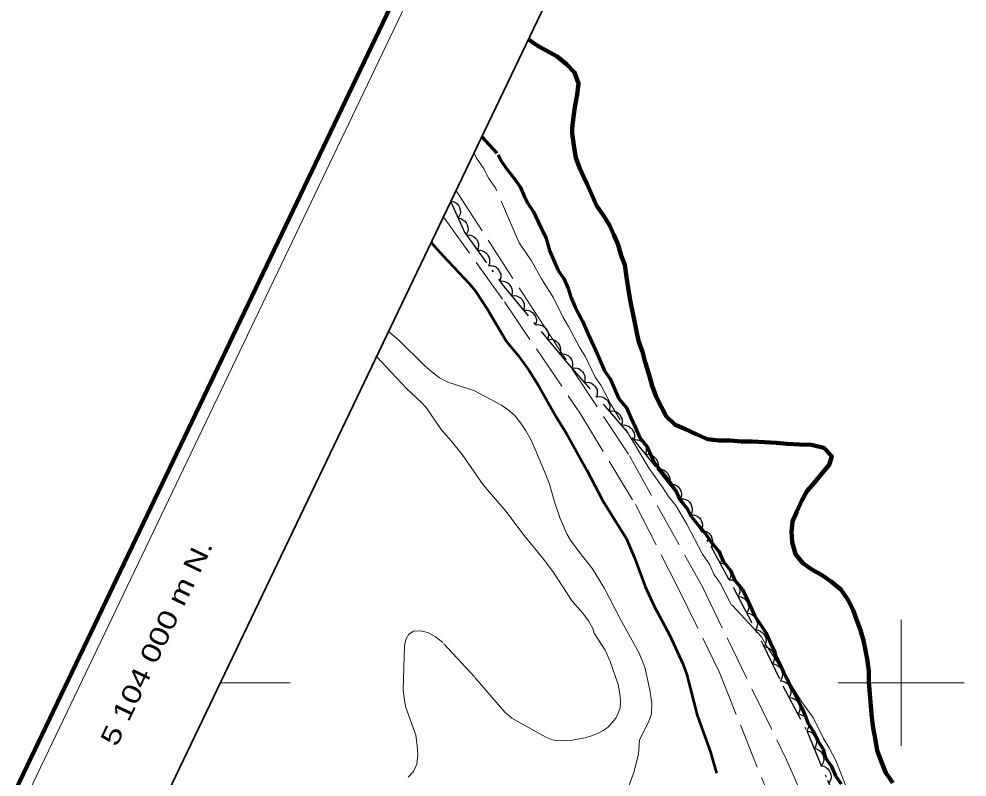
# Model space of a CAD drawing. Extents: x 356765 to 358572, y 5103174 to 5104650.
# Drawn here: x 356830 to 356905.2, y 5103992.5 to 5104052.7 of the extents above; entities that cross this region are included whole.
import ezdxf
from ezdxf.enums import TextEntityAlignment as Align

# ---------------------------------------------------------------- set-up
doc = ezdxf.new("R2010")
doc.units = 0
doc.header["$LTSCALE"] = 0.6
for name, pattern in [('DOT_DASHED', [7.7, 5, -1.2, 0.3, -1.2]), ('LONG_DASHED', [7.5, 6, -1.5]), ('MEDIUM_DASHED', [4.5, 3, -1.5])]:
    doc.linetypes.add(name, pattern=pattern)
for name, color, linetype, lineweight in [('1', 7, 'Continuous', 53), ('2', 7, 'Continuous', 13), ('4', 7, 'Continuous', 90), ('44', 7, 'Continuous', 25), ('60', 7, 'Continuous', 13), ('61', 7, 'Continuous', 13), ('7', 7, 'MEDIUM_DASHED', 70)]:
    doc.layers.add(name, color=color, linetype=linetype, lineweight=lineweight)

msp = doc.modelspace()

# ---------------------------------------------------------------- linework, layer by layer
at = {"layer": '1', "linetype": 'LONG_DASHED'}
msp.add_lwpolyline([(356862.66, 5104035.01), (356863.6, 5104033.95), (356865.74, 5104031.69), (356866.24, 5104031.07), (356867.12, 5104029.7), (356868.66, 5104027.12), (356869.59, 5104026), (356870.45, 5104024.82), (356871.21, 5104023.61), (356872.62, 5104021.13), (356873.44, 5104019.8), (356875.05, 5104016.88), (356876.32, 5104014.45), (356878.16, 5104011.5), (356878.8, 5104010), (356879.69, 5104007.65), (356880.4, 5104006.09), (356881.6, 5104003.8), (356882.71, 5104001.44), (356882.98, 5104000.63), (356883.81, 5103997.43), (356884.86, 5103994.49), (356885.34, 5103992.82)], dxfattribs=at)
at = {"layer": '2', "linetype": 'LONG_DASHED'}
for points in [[(356886.62, 5104006.13), (356886.54, 5104006.17), (356885.68, 5104007.83), (356885.14, 5104008.63), (356884.79, 5104009.42), (356884.24, 5104010.22), (356882.99, 5104012.6), (356882.12, 5104014.07), (356881.53, 5104014.79), (356881.06, 5104015.55), (356880, 5104017.03), (356876.97, 5104022.08), (356876.15, 5104023.63), (356875.71, 5104024.27), (356874.93, 5104025.89), (356874.46, 5104026.65), (356873.6, 5104028.31), (356873.13, 5104029.07), (356872.39, 5104030.57), (356871.44, 5104032.08), (356870.66, 5104033.51), (356869.67, 5104034.95), (356867.81, 5104039.25), (356867.26, 5104040.05), (356866.83, 5104040.88), (356866.29, 5104041.68), (356866.08, 5104042.13)], [(356864.64, 5104039.12), (356864.78, 5104038.93), (356871.41, 5104028.67), (356878.44, 5104018.03), (356884.22, 5104007.61), (356890.91, 5103993.87), (356897.31, 5103979.51), (356902.18, 5103967.99), (356905.03, 5103961.08), (356905.73, 5103956.92), (356906.05, 5103951.45), (356907.04, 5103946.26), (356907.65, 5103944.38), (356908.61, 5103941.88), (356909.24, 5103940.54), (356910.06, 5103938.2), (356910.5, 5103936.09)], [(356863.64, 5104037.05), (356868.51, 5104030.25), (356874.49, 5104021.45), (356878.9, 5104014.17), (356882.28, 5104007.58), (356885.58, 5104000.83), (356889.17, 5103991.84), (356894.82, 5103979.94)], [(356859.27, 5104027.93), (356860.09, 5104027.25), (356862.18, 5104025.17), (356862.75, 5104024.69), (356863.36, 5104024.22), (356864.02, 5104023.88), (356866.07, 5104023.22), (356868.28, 5104022.05), (356868.8, 5104021.68), (356869.32, 5104021.23), (356869.79, 5104020.66), (356870.2, 5104020.01), (356870.59, 5104019.33), (356870.92, 5104018.62), (356871.83, 5104016.47), (356872.08, 5104015.78), (356872.47, 5104014.38), (356872.93, 5104013.05), (356873.45, 5104011.84), (356873.75, 5104011.33), (356874.4, 5104010.42), (356875.5, 5104009.04), (356876.46, 5104007.5), (356877.67, 5104005.13), (356879.2, 5104002.34), (356879.64, 5104001.24), (356880.06, 5103999.45), (356880.21, 5103998.38), (356880.19, 5103997.54), (356879.94, 5103996.88), (356879.22, 5103995.47), (356879.15, 5103994.34), (356878.77, 5103992.88), (356878.31, 5103991.58)], [(356858.32, 5104025.96), (356858.35, 5104025.93), (356860.72, 5104023.38), (356861.95, 5104022.24), (356862.28, 5104021.88), (356863.49, 5104020.13), (356864.28, 5104019.22), (356865.14, 5104018.13), (356866.81, 5104015.72), (356868.61, 5104013.63), (356870.08, 5104011.71), (356871.64, 5104009.78), (356872.39, 5104008.75), (356873.88, 5104006.49), (356874.73, 5104005.53), (356875.18, 5104004.91), (356875.52, 5104004.3), (356875.63, 5104003.94), (356876.5, 5104002.59), (356876.91, 5104001.7), (356877.54, 5103999.86), (356877.7, 5103998.95), (356877.73, 5103998.47), (356877.69, 5103998.01), (356877.54, 5103997.59), (356877.34, 5103997.2), (356876.75, 5103996.48), (356876.35, 5103996.2), (356875.89, 5103995.98), (356875.43, 5103995.78), (356874.92, 5103995.63), (356873.89, 5103995.45), (356872.83, 5103995.38), (356872.32, 5103995.46), (356871.79, 5103995.68), (356869.08, 5103997.19), (356868.53, 5103997.66), (356866.14, 5104000.45), (356863.61, 5104003.19), (356863.04, 5104003.65), (356862.41, 5104004), (356861.8, 5104004.13), (356861.28, 5104004.09), (356860.92, 5104003.86), (356860.68, 5104003.45), (356860.57, 5104002.93), (356860.46, 5103999.44), (356860.53, 5103998.76), (356860.68, 5103998.05), (356861.47, 5103995.83), (356861.58, 5103995.01), (356861.63, 5103994.24), (356861.54, 5103993.53), (356861.29, 5103992.95), (356860.86, 5103992.49)]]:
    msp.add_lwpolyline(points, dxfattribs=at)
at = {"layer": '2'}
for points in [[(356894.83, 5103993.83), (356894.3, 5103994.82), (356893.83, 5103995.58), (356893.05, 5103997.2), (356892.1, 5103998.52), (356889.85, 5104002.15), (356889.31, 5104002.94), (356888.91, 5104003.66), (356886.62, 5104006.13)], [(356912.18, 5103936.61), (356911.1, 5103939.29), (356909.98, 5103942.98), (356909.67, 5103943.84), (356907.82, 5103951), (356907.01, 5103953.83), (356906.63, 5103955.62), (356905.82, 5103958.44), (356905.63, 5103959.34), (356905.33, 5103961.29), (356903.99, 5103965.99), (356903.84, 5103966.96), (356903.14, 5103969.63), (356903.03, 5103970.48), (356902.52, 5103972.25), (356902.14, 5103974.04), (356901.87, 5103974.98), (356900.35, 5103979.19), (356900.08, 5103980.13), (356899.69, 5103981.04), (356899.43, 5103981.98), (356898.56, 5103984.34), (356894.83, 5103993.83)]]:
    msp.add_lwpolyline(points, dxfattribs=at)
at = {"layer": '4'}
for points in [[(356870.39, 5104051.12), (356871.11, 5104050.63), (356871.87, 5104050.2), (356872.7, 5104049.74), (356873.45, 5104049.12), (356874.08, 5104048.48), (356874.39, 5104047.61), (356874.27, 5104046.69), (356874.12, 5104045.88), (356874, 5104044.96), (356873.88, 5104044.04), (356873.87, 5104043.65), (356874.02, 5104042.68), (356874.17, 5104041.7), (356874.48, 5104040.84), (356874.8, 5104040.16), (356875.08, 5104039.61), (356875.82, 5104037.91), (356876.37, 5104037.11), (356876.84, 5104036.36), (356877.19, 5104035.57), (356877.54, 5104034.78), (356877.78, 5104033.95), (356878.06, 5104033.2), (356878.21, 5104032.23), (356878.32, 5104031.37), (356878.48, 5104030.4), (356878.67, 5104029.5), (356878.86, 5104028.6), (356878.99, 5104027.94), (356879.15, 5104027.16), (356879.46, 5104026.29), (356879.69, 5104025.47), (356879.96, 5104024.53), (356880.23, 5104023.59), (356880.54, 5104022.72), (356880.97, 5104021.89), (356881.36, 5104021.18), (356882.07, 5104020.48), (356882.87, 5104020.14), (356883.74, 5104019.75), (356884.62, 5104019.36), (356885.54, 5104019.24), (356886.44, 5104019.24), (356887.29, 5104019.16), (356888.18, 5104019.16), (356889.15, 5104019.11), (356890.11, 5104019.06), (356890.96, 5104018.99), (356891.93, 5104018.94), (356892.9, 5104018.9), (356893.86, 5104018.66), (356894.49, 5104018.01), (356894.3, 5104017.32), (356893.73, 5104016.65), (356893.12, 5104015.91), (356892.54, 5104015.24), (356892.12, 5104014.48), (356891.73, 5104013.61), (356891.39, 5104012.82), (356891.31, 5104011.97), (356891.35, 5104011.16), (356891.62, 5104010.21), (356892.21, 5104009.49), (356892.92, 5104008.99), (356893.76, 5104008.53), (356894.47, 5104008.03), (356895.22, 5104007.42), (356895.77, 5104006.62), (356896.2, 5104005.78), (356896.47, 5104005.04), (356896.78, 5104004.17), (356897.02, 5104003.35), (356897.18, 5104002.57)], [(356897.18, 5104002.57), (356897.3, 5104001.9), (356897.45, 5104000.93), (356897.45, 5104000.04), (356897.53, 5103999.11), (356897.6, 5103998.18), (356897.68, 5103997.24), (356897.79, 5103996.39), (356897.95, 5103995.61), (356898.1, 5103994.63), (356898.41, 5103993.77), (356898.8, 5103992.86), (356899.35, 5103992.06)]]:
    msp.add_lwpolyline(points, dxfattribs=at)
at = {"layer": '44'}
for points in [[(356864.22, 5104038.28), (356864.42, 5104038.24), (356864.61, 5104038.15), (356864.74, 5104038.05), (356864.85, 5104037.91), (356864.94, 5104037.75), (356864.99, 5104037.57), (356865.01, 5104037.41), (356864.98, 5104037.23), (356864.92, 5104037.06), (356864.83, 5104036.9)], [(356864.83, 5104036.9), (356865.03, 5104036.87), (356865.21, 5104036.77), (356865.35, 5104036.68), (356865.46, 5104036.54), (356865.55, 5104036.38), (356865.6, 5104036.2), (356865.62, 5104036.03), (356865.59, 5104035.86), (356865.53, 5104035.69), (356865.43, 5104035.53)], [(356865.49, 5104035.56), (356865.69, 5104035.57), (356865.89, 5104035.52), (356866.04, 5104035.45), (356866.18, 5104035.34), (356866.3, 5104035.2), (356866.39, 5104035.03), (356866.44, 5104034.88), (356866.45, 5104034.7), (356866.43, 5104034.52), (356866.37, 5104034.35)], [(356866.37, 5104034.35), (356866.58, 5104034.36), (356866.77, 5104034.3), (356866.92, 5104034.24), (356867.06, 5104034.13), (356867.18, 5104033.99), (356867.27, 5104033.82), (356867.32, 5104033.67), (356867.33, 5104033.49), (356867.31, 5104033.31), (356867.25, 5104033.14)], [(356867.25, 5104033.14), (356867.46, 5104033.14), (356867.65, 5104033.09), (356867.81, 5104033.03), (356867.94, 5104032.92), (356868.06, 5104032.78), (356868.15, 5104032.6), (356868.21, 5104032.45), (356868.21, 5104032.28), (356868.19, 5104032.09), (356868.13, 5104031.92)], [(356868.1, 5104031.9), (356868.31, 5104031.92), (356868.51, 5104031.88), (356868.67, 5104031.83), (356868.81, 5104031.73), (356868.94, 5104031.59), (356869.04, 5104031.43), (356869.1, 5104031.28), (356869.12, 5104031.1), (356869.11, 5104030.92), (356869.06, 5104030.75)], [(356869.06, 5104030.75), (356869.27, 5104030.77), (356869.47, 5104030.73), (356869.62, 5104030.67), (356869.77, 5104030.57), (356869.9, 5104030.44), (356869.99, 5104030.27), (356870.06, 5104030.12), (356870.08, 5104029.95), (356870.07, 5104029.76), (356870.02, 5104029.59)], [(356870.02, 5104029.59), (356870.23, 5104029.61), (356870.43, 5104029.57), (356870.58, 5104029.52), (356870.72, 5104029.42), (356870.85, 5104029.28), (356870.95, 5104029.12), (356871.02, 5104028.97), (356871.04, 5104028.79), (356871.03, 5104028.61), (356870.98, 5104028.44)], [(356870.98, 5104028.44), (356871.18, 5104028.46), (356871.38, 5104028.42), (356871.54, 5104028.36), (356871.68, 5104028.26), (356871.81, 5104028.13), (356871.91, 5104027.96), (356871.97, 5104027.82), (356871.99, 5104027.64), (356871.98, 5104027.45), (356871.93, 5104027.28)], [(356871.93, 5104027.28), (356872.14, 5104027.3), (356872.34, 5104027.26), (356872.5, 5104027.21), (356872.64, 5104027.11), (356872.77, 5104026.98), (356872.87, 5104026.81), (356872.93, 5104026.66), (356872.95, 5104026.49), (356872.94, 5104026.3), (356872.89, 5104026.13)], [(356872.88, 5104026.12), (356873.09, 5104026.14), (356873.29, 5104026.11), (356873.44, 5104026.06), (356873.59, 5104025.96), (356873.72, 5104025.83), (356873.82, 5104025.67), (356873.89, 5104025.52), (356873.92, 5104025.35), (356873.91, 5104025.16), (356873.86, 5104024.99)], [(356873.86, 5104024.99), (356874.07, 5104025.01), (356874.27, 5104024.98), (356874.43, 5104024.93), (356874.57, 5104024.83), (356874.71, 5104024.7), (356874.81, 5104024.54), (356874.88, 5104024.39), (356874.9, 5104024.21), (356874.89, 5104024.03), (356874.85, 5104023.85)], [(356874.85, 5104023.85), (356875.06, 5104023.88), (356875.26, 5104023.84), (356875.41, 5104023.79), (356875.56, 5104023.7), (356875.69, 5104023.57), (356875.79, 5104023.4), (356875.86, 5104023.26), (356875.88, 5104023.08), (356875.88, 5104022.9), (356875.83, 5104022.72)], [(356875.83, 5104022.72), (356876.04, 5104022.75), (356876.24, 5104022.71), (356876.4, 5104022.66), (356876.54, 5104022.56), (356876.68, 5104022.44), (356876.78, 5104022.27), (356876.85, 5104022.13), (356876.87, 5104021.95), (356876.86, 5104021.77), (356876.82, 5104021.59)], [(356876.81, 5104021.59), (356877.02, 5104021.61), (356877.22, 5104021.58), (356877.38, 5104021.53), (356877.52, 5104021.43), (356877.66, 5104021.3), (356877.76, 5104021.13), (356877.82, 5104020.99), (356877.85, 5104020.81), (356877.84, 5104020.63), (356877.79, 5104020.45)], [(356877.79, 5104020.45), (356878, 5104020.48), (356878.2, 5104020.44), (356878.36, 5104020.39), (356878.5, 5104020.29), (356878.63, 5104020.16), (356878.73, 5104020), (356878.8, 5104019.85), (356878.82, 5104019.67), (356878.82, 5104019.49), (356878.77, 5104019.31)], [(356878.76, 5104019.31), (356878.97, 5104019.32), (356879.17, 5104019.28), (356879.33, 5104019.22), (356879.47, 5104019.12), (356879.59, 5104018.98), (356879.69, 5104018.82), (356879.75, 5104018.67), (356879.77, 5104018.49), (356879.75, 5104018.31), (356879.7, 5104018.13)], [(356879.7, 5104018.13), (356879.91, 5104018.15), (356880.1, 5104018.11), (356880.26, 5104018.05), (356880.4, 5104017.94), (356880.53, 5104017.81), (356880.62, 5104017.64), (356880.68, 5104017.49), (356880.7, 5104017.32), (356880.69, 5104017.13), (356880.63, 5104016.96)], [(356880.63, 5104016.96), (356880.84, 5104016.98), (356881.04, 5104016.93), (356881.19, 5104016.88), (356881.33, 5104016.77), (356881.46, 5104016.64), (356881.55, 5104016.47), (356881.62, 5104016.32), (356881.63, 5104016.14), (356881.62, 5104015.96), (356881.56, 5104015.79)], [(356881.56, 5104015.79), (356881.77, 5104015.8), (356881.97, 5104015.76), (356882.13, 5104015.7), (356882.27, 5104015.6), (356882.39, 5104015.46), (356882.49, 5104015.29), (356882.55, 5104015.14), (356882.57, 5104014.97), (356882.55, 5104014.78), (356882.5, 5104014.61)], [(356882.51, 5104014.62), (356882.72, 5104014.61), (356882.91, 5104014.55), (356883.06, 5104014.48), (356883.19, 5104014.36), (356883.3, 5104014.21), (356883.37, 5104014.03), (356883.42, 5104013.88), (356883.42, 5104013.7), (356883.38, 5104013.52), (356883.31, 5104013.35)], [(356883.31, 5104013.35), (356883.52, 5104013.35), (356883.71, 5104013.28), (356883.86, 5104013.21), (356883.99, 5104013.09), (356884.1, 5104012.94), (356884.18, 5104012.77), (356884.22, 5104012.61), (356884.22, 5104012.43), (356884.19, 5104012.25), (356884.12, 5104012.09)], [(356884.12, 5104012.09), (356884.32, 5104012.08), (356884.52, 5104012.02), (356884.67, 5104011.94), (356884.79, 5104011.82), (356884.91, 5104011.68), (356884.98, 5104011.5), (356885.03, 5104011.34), (356885.02, 5104011.17), (356884.99, 5104010.98), (356884.92, 5104010.82)], [(356884.92, 5104010.82), (356885.13, 5104010.8), (356885.31, 5104010.72), (356885.46, 5104010.64), (356885.58, 5104010.51), (356885.68, 5104010.36), (356885.74, 5104010.18), (356885.78, 5104010.02), (356885.76, 5104009.84), (356885.72, 5104009.66), (356885.64, 5104009.5)], [(356885.64, 5104009.5), (356885.84, 5104009.48), (356886.03, 5104009.4), (356886.17, 5104009.32), (356886.3, 5104009.19), (356886.4, 5104009.04), (356886.46, 5104008.86), (356886.5, 5104008.7), (356886.48, 5104008.52), (356886.44, 5104008.34), (356886.35, 5104008.18)], [(356886.35, 5104008.18), (356886.56, 5104008.17), (356886.75, 5104008.09), (356886.89, 5104008.01), (356887.01, 5104007.88), (356887.12, 5104007.72), (356887.18, 5104007.54), (356887.21, 5104007.38), (356887.2, 5104007.21), (356887.15, 5104007.03), (356887.07, 5104006.87)], [(356887.06, 5104006.86), (356887.27, 5104006.84), (356887.45, 5104006.76), (356887.59, 5104006.67), (356887.71, 5104006.54), (356887.81, 5104006.38), (356887.87, 5104006.2), (356887.9, 5104006.04), (356887.88, 5104005.87), (356887.83, 5104005.69), (356887.75, 5104005.53)], [(356887.75, 5104005.53), (356887.96, 5104005.5), (356888.14, 5104005.42), (356888.28, 5104005.34), (356888.4, 5104005.21), (356888.5, 5104005.05), (356888.56, 5104004.87), (356888.59, 5104004.71), (356888.57, 5104004.53), (356888.52, 5104004.35), (356888.44, 5104004.2)], [(356888.44, 5104004.2), (356888.64, 5104004.17), (356888.83, 5104004.09), (356888.97, 5104004), (356889.09, 5104003.87), (356889.19, 5104003.72), (356889.25, 5104003.54), (356889.28, 5104003.38), (356889.26, 5104003.2), (356889.21, 5104003.02), (356889.13, 5104002.86)], [(356889.12, 5104002.86), (356889.33, 5104002.83), (356889.51, 5104002.74), (356889.65, 5104002.65), (356889.76, 5104002.52), (356889.86, 5104002.36), (356889.91, 5104002.18), (356889.94, 5104002.02), (356889.92, 5104001.84), (356889.86, 5104001.67), (356889.77, 5104001.51)], [(356889.77, 5104001.51), (356889.98, 5104001.48), (356890.16, 5104001.39), (356890.3, 5104001.3), (356890.42, 5104001.17), (356890.51, 5104001.01), (356890.56, 5104000.83), (356890.59, 5104000.67), (356890.57, 5104000.49), (356890.51, 5104000.31), (356890.42, 5104000.16)], [(356890.41, 5104000.15), (356890.62, 5104000.13), (356890.8, 5104000.05), (356890.94, 5103999.96), (356891.06, 5103999.84), (356891.16, 5103999.68), (356891.22, 5103999.5), (356891.26, 5103999.34), (356891.24, 5103999.16), (356891.19, 5103998.98), (356891.11, 5103998.83)], [(356891.11, 5103998.83), (356891.32, 5103998.8), (356891.51, 5103998.72), (356891.65, 5103998.64), (356891.77, 5103998.51), (356891.87, 5103998.36), (356891.93, 5103998.17), (356891.96, 5103998.01), (356891.95, 5103997.84), (356891.9, 5103997.66), (356891.81, 5103997.5)], [(356891.81, 5103997.5), (356892.02, 5103997.48), (356892.21, 5103997.4), (356892.35, 5103997.31), (356892.47, 5103997.19), (356892.57, 5103997.03), (356892.63, 5103996.85), (356892.66, 5103996.69), (356892.65, 5103996.51), (356892.6, 5103996.33), (356892.52, 5103996.18)], [(356892.52, 5103996.18), (356892.72, 5103996.14), (356892.9, 5103996.04), (356893.04, 5103995.94), (356893.14, 5103995.8), (356893.23, 5103995.64), (356893.27, 5103995.45), (356893.29, 5103995.29), (356893.26, 5103995.12), (356893.2, 5103994.94), (356893.1, 5103994.79)], [(356893.1, 5103994.79), (356893.3, 5103994.75), (356893.48, 5103994.66), (356893.61, 5103994.56), (356893.72, 5103994.42), (356893.81, 5103994.25), (356893.85, 5103994.07), (356893.87, 5103993.91), (356893.84, 5103993.73), (356893.77, 5103993.56), (356893.68, 5103993.41)], [(356893.68, 5103993.41), (356893.88, 5103993.37), (356894.06, 5103993.27), (356894.19, 5103993.17), (356894.3, 5103993.03), (356894.38, 5103992.87), (356894.43, 5103992.68), (356894.45, 5103992.52), (356894.42, 5103992.35), (356894.35, 5103992.17), (356894.25, 5103992.02)]]:
    msp.add_lwpolyline(points, dxfattribs=at)
at = {"layer": '44', "linetype": 'DOT_DASHED'}
msp.add_lwpolyline([(356864.23, 5104038.28), (356864.27, 5104038.16), (356865.32, 5104035.79), (356868.46, 5104031.47), (356873.32, 5104025.61), (356876.34, 5104022.14), (356878.62, 5104019.49), (356880.6, 5104017), (356882.58, 5104014.51), (356884.9, 5104010.85), (356886.76, 5104007.44), (356889.05, 5104003.01), (356890.61, 5103999.77), (356892.54, 5103996.13), (356894.15, 5103992.27), (356895.69, 5103988.64), (356897.27, 5103984.01), (356898.84, 5103979.38), (356900.18, 5103974.68), (356901.77, 5103968.66), (356903.38, 5103963.02), (356905.19, 5103956.68), (356906.46, 5103952.22)], dxfattribs=at)
at = {"layer": '60', "lineweight": 158}
msp.add_lwpolyline([(356765.24, 5103856.84), (358192.2, 5103173.84), (358571.69, 5103966.7), (357144.73, 5104649.7)], close=True, dxfattribs=at)
at = {"layer": '60'}
msp.add_lwpolyline([(356766.57, 5103857.31), (358191.72, 5103175.17), (358570.35, 5103966.23), (357145.2, 5104648.37)], close=True, dxfattribs=at)
at = {"layer": '60', "lineweight": 35}
msp.add_lwpolyline([(356779.89, 5103862.01), (357952.48, 5103300.77), (358322.47, 5104073.79), (357149.88, 5104635.03)], close=True, dxfattribs=at)
at = {"layer": '61'}
for p, q in [((356900, 5103995), (356900, 5104005)), ((356851.48, 5104000), (356845.94, 5104000)), ((356895, 5104000), (356905, 5104000))]:
    msp.add_line(p, q, dxfattribs=at)
at = {"layer": '7'}
for points in [[(356866.68, 5104043.39), (356868, 5104041.95), (356868.28, 5104041.4), (356868.72, 5104040.76), (356869.31, 5104040.03), (356869.74, 5104039.4), (356870.1, 5104038.61), (356870.38, 5104038.05), (356870.82, 5104037.41), (356871.17, 5104036.62), (356871.46, 5104036.07), (356871.81, 5104035.28), (356872.08, 5104034.34), (356872.43, 5104033.55), (356872.78, 5104032.76), (356873.22, 5104032.12), (356873.57, 5104031.33), (356873.77, 5104030.62), (356874.13, 5104029.83), (356874.41, 5104029.28), (356874.7, 5104028.73), (356875.05, 5104027.94), (356875.4, 5104027.15), (356875.76, 5104026.36), (356876.11, 5104025.57), (356876.46, 5104024.78), (356876.9, 5104024.14), (356877.25, 5104023.35), (356877.6, 5104022.56), (356878.19, 5104021.84), (356878.54, 5104021.05), (356878.9, 5104020.26), (356879.25, 5104019.47), (356879.84, 5104018.74), (356880.19, 5104017.95), (356880.47, 5104017.4), (356881.06, 5104016.68), (356881.65, 5104015.95), (356882.09, 5104015.31)], [(356882.09, 5104015.31), (356882.44, 5104014.52), (356883.03, 5104013.8), (356883.31, 5104013.25), (356883.9, 5104012.52), (356884.49, 5104011.8), (356884.93, 5104011.16), (356885.52, 5104010.44), (356885.87, 5104009.65), (356886.46, 5104008.92), (356886.81, 5104008.13), (356887.4, 5104007.41), (356887.68, 5104006.86), (356888.04, 5104006.07), (356888.39, 5104005.28), (356888.83, 5104004.64), (356889.26, 5104004), (356889.61, 5104003.21), (356889.97, 5104002.42), (356890.03, 5104002.18), (356890.39, 5104001.39), (356890.67, 5104000.84), (356890.96, 5104000.29), (356891.31, 5103999.5), (356891.53, 5103999.18), (356891.81, 5103998.62), (356892.1, 5103998.07), (356892.45, 5103997.28), (356892.59, 5103996.81), (356893.02, 5103996.17), (356893.38, 5103995.38), (356893.81, 5103994.74), (356894.01, 5103994.03), (356894.45, 5103993.4), (356894.8, 5103992.61), (356895.24, 5103991.97)]]:
    msp.add_lwpolyline(points, dxfattribs=at)

# ---------------------------------------------------------------- texts
at = {"layer": '61', "width": 1.3}
msp.add_text(' 5 104 000 m N.', height=1.5, rotation=64.42, dxfattribs=at).set_placement((356841.396, 5104002.5662), align=Align.CENTER)

doc.saveas('drawing.dxf')
